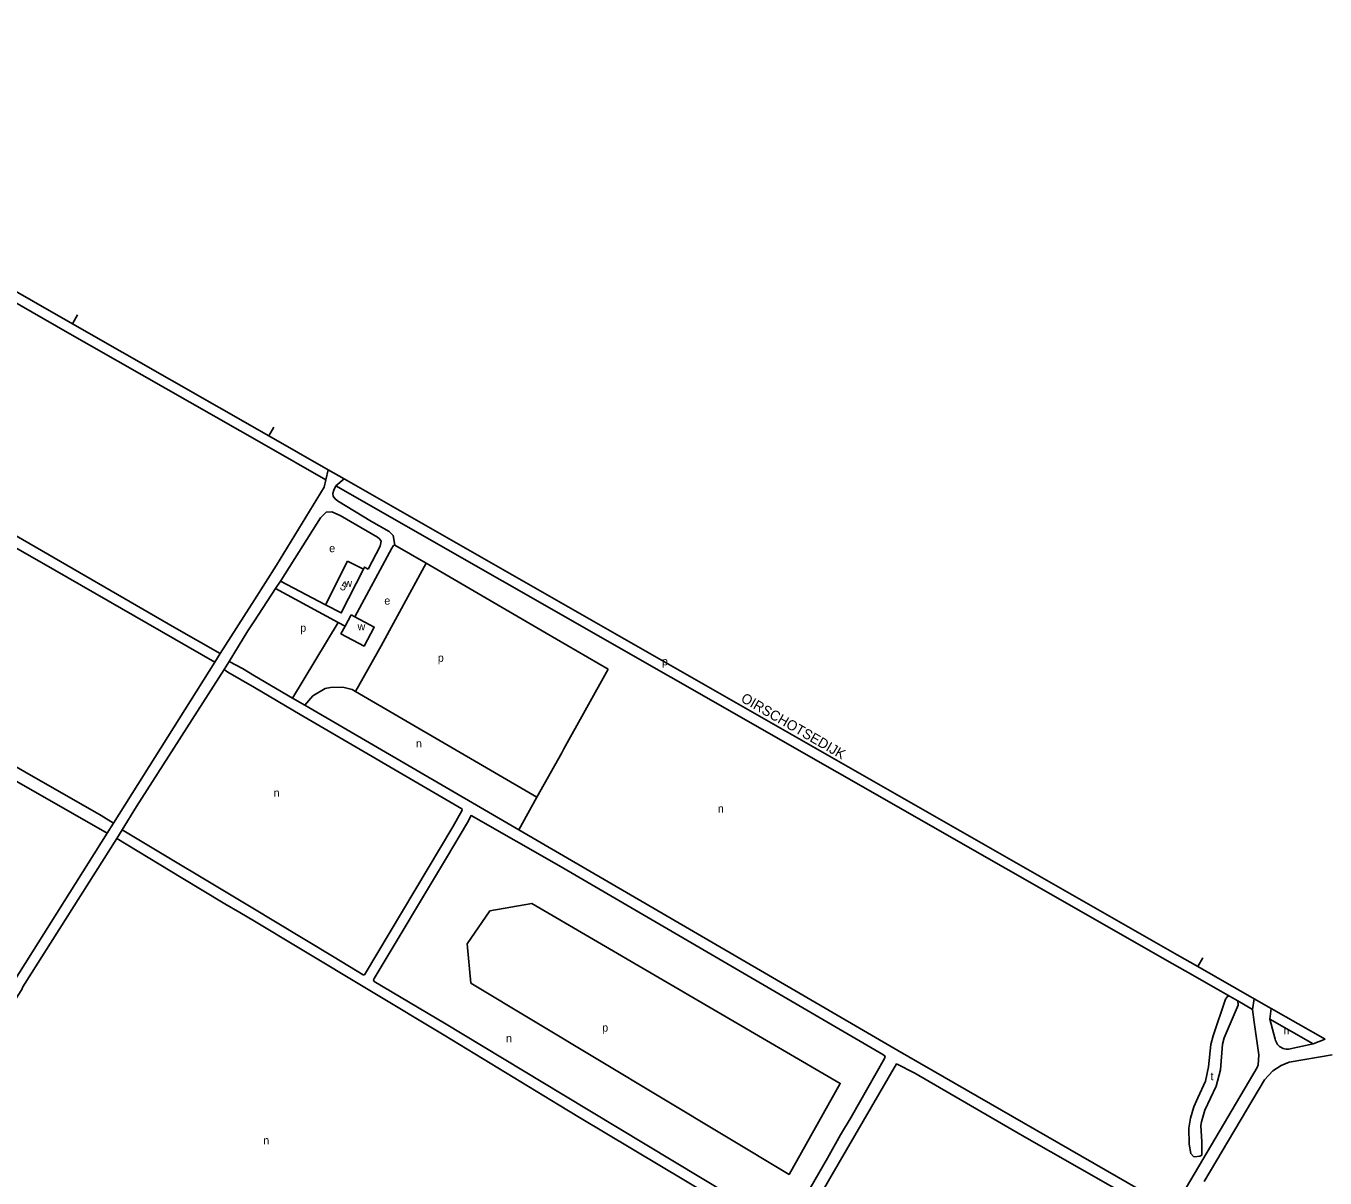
# Model space of a CAD drawing. Extents: x 156521 to 159067, y 384230 to 386095.
# Drawn here: x 157936 to 158585, y 385200 to 385776 of the extents above; entities that cross this region are included whole.
import ezdxf

# ---------------------------------------------------------------- set-up
doc = ezdxf.new("R2010")
doc.units = 0
for name, color, linetype in [('BLT_Basislijn', 7, 'Continuous'), ('BLT_Bebouwing', 7, 'Continuous'), ('BLT_Centroide', 7, 'Continuous'), ('BLT_Huisnummer', 7, 'Continuous'), ('BLT_Straatnaam', 7, 'Continuous'), ('BLT_Vlakafsluiter', 7, 'Continuous')]:
    doc.layers.add(name, color=color, linetype=linetype)

msp = doc.modelspace()

# ---------------------------------------------------------------- linework, layer by layer
at = {"layer": 'BLT_Basislijn'}
for p, q in [((157698.67, 385775.91), (157959.07, 385627.15)), ((157793.51, 385715.98), (157956.59, 385622.81)), ((158057.26, 385571.06), (157959.07, 385627.15)), ((157956.59, 385622.81), (158054.78, 385566.72)), ((158057.26, 385571.06), (158086.92, 385554.11)), ((158054.78, 385566.72), (158085.68, 385549.06)), ((158085.68, 385549.06), (158086.92, 385554.11)), ((158086.92, 385554.11), (158094.8, 385549.61)), ((158094.8, 385549.61), (158090.75, 385546.17)), ((158094.8, 385549.61), (158511.08, 385311.81)), ((158090.75, 385546.17), (158508.6, 385307.46)), ((158135.89, 385507.53), (158120.11, 385516.52)), ((158113.24, 385466.2), (158135.89, 385507.53)), ((158195.8, 385472.57), (158135.89, 385507.53)), ((158060.54, 385494.76), (158062.99, 385498.51)), ((158085.45, 385486.62), (158062.99, 385498.51)), ((158060.54, 385494.76), (158050, 385478.59)), ((158060.54, 385494.76), (158091.9, 385477.8)), ((158050, 385489.21), (158032.89, 385462.26)), ((158069.03, 385439.97), (158091.9, 385477.8)), ((158095.26, 385476.03), (158091.9, 385477.8)), ((158226.68, 385454.55), (158195.8, 385472.57)), ((158100.48, 385443.4), (158113.24, 385466.2)), ((157979.59, 385377.6), (158030.19, 385458.03)), ((158030.19, 385458.03), (158032.89, 385462.26)), ((158037.41, 385458.37), (158034.87, 385454.43)), ((158050, 385451.23), (158069.03, 385439.97)), ((158204.65, 385414.71), (158226.68, 385454.55)), ((158075.15, 385436.45), (158069.03, 385439.97)), ((158191.15, 385390.61), (158100.48, 385443.4)), ((158182.12, 385374.2), (158075.15, 385436.45)), ((158191.15, 385390.61), (158203.62, 385412.65)), ((158204.65, 385414.71), (158203.62, 385412.65)), ((158191.15, 385390.61), (158182.12, 385374.2)), ((157979.59, 385377.6), (157976.36, 385372.58)), ((157983.98, 385374.26), (157981.19, 385369.95)), ((158050, 385334.61), (157983.98, 385374.26)), ((157923.31, 385288.07), (157976.36, 385372.58)), ((158511.08, 385311.81), (158521.42, 385305.9)), ((158518.94, 385301.55), (158508.6, 385307.46)), ((158518.94, 385301.55), (158537.2, 385291.12)), ((158521.42, 385305.9), (158549.54, 385289.83)), ((158537.2, 385291.12), (158541.44, 385288.7)), ((158541.44, 385288.7), (158548.75, 385284.52)), ((158548.75, 385284.52), (158549.54, 385289.83)), ((158549.54, 385289.83), (158558.08, 385284.95)), ((158548.75, 385284.52), (158549.58, 385278.11)), ((158557.29, 385279.65), (158558.08, 385284.95)), ((158558.08, 385284.95), (158584.94, 385269.61)), ((158557.29, 385279.65), (158560.07, 385269.56)), ((158557.29, 385279.65), (158579.02, 385267.23)), ((158579.02, 385267.23), (158584.94, 385269.61)), ((158567.46, 385264.79), (158579.02, 385267.23))]:
    msp.add_line(p, q, dxfattribs=at)
for points in [[(158032.89, 385462.26), (158010, 385475.26), (157832.71, 385578), (157832.29, 385579.31), (157833.26, 385581.39), (157846.71, 385604.76), (157846.39, 385606.12), (157842.79, 385607.72), (157841.96, 385607.18), (157828.08, 385581.55), (157827.35, 385580.81), (157826.97, 385580.81), (157769.79, 385613.1)], [(157979.59, 385377.6), (157973.38, 385381.45), (157782.55, 385490.45), (157782.55, 385490.99), (157786, 385497.66), (157828.62, 385572.98), (157831.62, 385571.55), (157943.63, 385507.74), (158030.19, 385458.03)], [(158085.68, 385549.06), (158084.78, 385545.38), (158060.97, 385506.48), (158050, 385489.21)], [(158120.11, 385516.52), (158119.39, 385521.28), (158117.32, 385523.35), (158108.44, 385528.27), (158091.42, 385538.55), (158090.1, 385539.74), (158089.42, 385540.92), (158089.13, 385542.31), (158089.67, 385543.89), (158090.75, 385546.17)], [(158062.99, 385498.51), (158063.29, 385498.97), (158083, 385530.13), (158085.77, 385532.89), (158088.73, 385533.14), (158092.8, 385531.31), (158111.43, 385520.55), (158112.7, 385519.43), (158113.34, 385518.41), (158112.78, 385515.9), (158106.86, 385504.45)], [(158120.11, 385516.52), (158119.51, 385516.26), (158118.73, 385515), (158100.18, 385480.68)], [(158104.47, 385504.48), (158105.03, 385505.5), (158106.86, 385504.45)], [(158050, 385478.59), (158046.76, 385473.62), (158037.41, 385458.37)], [(158037.41, 385458.37), (158044, 385454.78), (158050, 385451.23)], [(158034.87, 385454.43), (157991.1, 385385.9), (157983.98, 385374.26)], [(158034.87, 385454.43), (158036.64, 385453.07), (158050, 385445.27)], [(158050, 385445.27), (158072.93, 385431.89)], [(158100.48, 385443.4), (158098.87, 385444.32), (158094.17, 385445.51), (158087.93, 385445.32), (158085.39, 385444.81), (158079.15, 385441.17), (158075.15, 385436.45)], [(158072.93, 385431.89), (158153.69, 385384.77), (158153.83, 385384.11), (158149.18, 385375.73), (158104.98, 385301.7), (158104.3, 385301.69), (158089.91, 385310.63), (158059.64, 385328.82)], [(157923.31, 385288.07), (157908.56, 385293.23), (157897.74, 385301.61), (157873.38, 385316.89), (157837.15, 385332.33), (157838.33, 385334.97), (157884.91, 385421.87), (157885.8, 385423.21), (157886.88, 385423.7), (157976.36, 385372.58)], [(158145.89, 385360.28), (158156.41, 385377.85), (158158.23, 385381.39), (158202.14, 385356.42), (158364.02, 385261.92), (158365.12, 385261.1), (158364.85, 385259.9), (158348.2, 385230.68), (158342.84, 385221.87)], [(158182.12, 385374.2), (158291.65, 385310.46), (158371.52, 385264.04), (158509.19, 385184.74)], [(157976.34, 385157.64), (157942.43, 385171.89), (157884.65, 385195.02), (157881.29, 385197.34), (157879.08, 385199.55), (157877.9, 385202.27), (157877.79, 385205.87), (157879.29, 385210.09), (157933.78, 385294.51), (157934.28, 385295.7), (157981.19, 385369.95)], [(157981.19, 385369.95), (158013.41, 385350.4)], [(158145.89, 385360.28), (158109.84, 385299.95), (158109.55, 385299.33), (158109.88, 385298.48), (158145.04, 385277.7), (158203.7, 385242.18)], [(158013.41, 385350.4), (158035.14, 385337.21), (158042.72, 385332.9), (158050, 385328.53)], [(158059.64, 385328.82), (158050, 385334.61)], [(158050, 385328.53), (158072.21, 385315.2)], [(158072.21, 385315.2), (158144.77, 385271.64), (158202.32, 385236.66)], [(158521.33, 385240.25), (158519.32, 385235.8), (158517.67, 385230.23), (158516.95, 385225.2), (158517.11, 385217.13), (158517.85, 385212.42), (158519.16, 385211.03), (158519.84, 385210.85), (158522.44, 385211.14), (158523.33, 385211.67), (158523.39, 385218.36), (158522.95, 385226.52), (158523.24, 385228.38), (158524.93, 385234.12), (158530.56, 385246.11), (158532.63, 385254.33), (158533.74, 385267.16), (158534.58, 385270.3), (158541.54, 385286.64), (158541.44, 385288.7)], [(158537.2, 385291.12), (158536.13, 385291), (158535.18, 385289.67), (158529.06, 385271.25), (158527.85, 385267), (158526.74, 385255.76), (158525.15, 385248.69), (158521.33, 385240.25)], [(158549.58, 385278.11), (158551.86, 385261.78), (158551.57, 385256.78), (158551.09, 385255.51), (158509.19, 385184.74)], [(158560.07, 385269.56), (158560.26, 385268.88), (158560.52, 385268.23), (158560.85, 385267.61), (158561.26, 385267.03), (158561.72, 385266.5), (158562.25, 385266.03), (158562.82, 385265.61), (158563.43, 385265.27), (158564.09, 385265), (158564.76, 385264.8), (158565.46, 385264.69), (158566.16, 385264.65), (158566.87, 385264.69), (158567.46, 385264.79)], [(158454.18, 385091.87), (158321.77, 385171.77), (158322.73, 385173.94), (158337.59, 385199.98), (158370.85, 385257.22), (158379.91, 385252.58), (158433.65, 385221.48), (158506.33, 385179.97)], [(158524.55, 385198.42), (158554.77, 385249.34), (158558.89, 385253.82), (158563, 385256.41), (158566.95, 385258.07), (158588.51, 385261.81)], [(158451.58, 385087.55), (158212.45, 385230.51), (158202.32, 385236.66)], [(158203.7, 385242.18), (158315.18, 385175.02), (158316.51, 385175.77), (158336.27, 385210.21), (158342.84, 385221.87)]]:
    msp.add_lwpolyline(points, dxfattribs=at)
msp.add_lwpolyline([(158167.6, 385333.73), (158188.53, 385337.49), (158342.68, 385247.54), (158317.15, 385202.06), (158158.18, 385297.69), (158156.28, 385317.2)], close=True, dxfattribs=at)
at = {"layer": 'BLT_Bebouwing'}
for p, q in [((158096.58, 385508.5), (158104.47, 385504.48)), ((158095.26, 385476.03), (158098.29, 385481.7)), ((158098.29, 385481.7), (158100.18, 385480.68))]:
    msp.add_line(p, q, dxfattribs=at)
for points in [[(158085.45, 385486.62), (158096.58, 385508.5)], [(158104.47, 385504.48), (158093.34, 385482.6), (158085.45, 385486.62)], [(158100.18, 385480.68), (158109.84, 385475.53), (158104.79, 385466.08), (158093.24, 385472.24), (158095.26, 385476.03)]]:
    msp.add_lwpolyline(points, dxfattribs=at)
at = {"layer": 'BLT_Vlakafsluiter'}
for p, q in [((157959.07, 385627.15), (157961.55, 385631.5)), ((158057.26, 385571.06), (158059.74, 385575.4)), ((158523.9, 385310.24), (158521.42, 385305.9))]:
    msp.add_line(p, q, dxfattribs=at)

# ---------------------------------------------------------------- texts
at = {"layer": 'BLT_Centroide'}
for s, p in [('e', (158087.35, 385512.97)), ('w', (158094.95, 385495.55)), ('e', (158114.9, 385486.77)), ('w', (158101.54, 385473.88)), ('p', (158072.9, 385473.21)), ('p', (158141.63, 385458.2)), ('p', (158253.61, 385456.42)), ('n', (158130.71, 385415.38)), ('n', (158059.57, 385390.78)), ('n', (158281.54, 385382.85)), ('p', (158223.75, 385273.41)), ('n', (158175.7, 385268.1)), ('n', (158564.19, 385271.98)), ('t', (158527.68, 385249.12)), ('n', (158054.42, 385217.07))]:
    msp.add_text(s, height=4, dxfattribs=at).set_placement(p)
at = {"layer": 'BLT_Huisnummer'}
msp.add_text('5', height=4, rotation=331.93571, dxfattribs=at).set_placement((158092.34, 385494.71))
at = {"layer": 'BLT_Straatnaam'}
msp.add_text('OIRSCHOTSEDIJK', height=5, rotation=330.03464, dxfattribs=at).set_placement((158292.65, 385438.59))

doc.saveas('drawing.dxf')
